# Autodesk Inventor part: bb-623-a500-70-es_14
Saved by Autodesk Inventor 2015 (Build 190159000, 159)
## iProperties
Created: 2022-04
Part Number: bb-623-a500-70-es_14
Checked By: TraceParts S.A.
Material: Generic
Catalog Web Link: www.traceparts.com
Document SubType Name: Modeling
Designer: TraceParts
Density: 1 g/cm^3
Appearance: Default
Company: TraceParts S.A.
Author: TraceParts
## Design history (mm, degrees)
feature "bb-623-a500-70-es_14.ipt"
body "Solid1"
